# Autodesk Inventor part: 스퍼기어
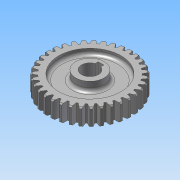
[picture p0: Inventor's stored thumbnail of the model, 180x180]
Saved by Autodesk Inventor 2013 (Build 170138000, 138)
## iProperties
Created: 2013-08
Part Number: 스퍼기어
Material: 강
Document SubType Name: Modeling
Designer: 한국산업디자인학원
Categories: <?xml version="1.0" encoding="UTF-16"?> <MemberInstance><Categories><FamilyTemplate><FamilyTemplateParameter ValueType="xs:double" Id="1" ObjectReferenceKey="da
Density: 1 g/cm^3
CustomPartVersion: 1
Author: 한국산업디자인학원
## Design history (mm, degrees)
sketch "Sketch1"
  geometry: C1 r 37 at (0, 0)
  constraints: 1 centre point
  dimensions: "d0" = 74 diameter of C1 (= da_da)
extrude "Extrusion1" new body sketch "Sketch1" distance "d1" = 15 (= da_b); taper "d2" = 0 deg
chamfer "모따기1" distance "d49" = 1; stored, may be unused: second distance "d50" = 2, angle "d51" = 45 deg
workplane "Work Plane2"
feature "피치 지름" dims "d4" = 10, "d5" = 0
workplane "Work Plane8"
workplane "Work Plane9"
feature "스퍼 기어" dims "da_b" = 15, "da_d" = 70, "da_aw" = 70, "da_da" = 74, "da_df" = 65, "da_dw" = 70, angle "da_beta" = 0 deg, "da_lefttooth" = 0, "da_righttooth" = 0
sketch "스케치3"
  geometry: L1 (-2.5, 7.071)-(-2.5, 9.8); L2 (-2.5, 9.8)-(2.5, 9.8); L3 (2.5, 9.8)-(2.5, 7.071); C1 r 27.5 at (0, 0); C2 r 12.5 at (0, 0); A1 r 36 centre (0, 0) between (-5.215, 35.62) and (-7.633, 35.181) reference; A2 r 7.5 centre (0, 0) between (-2.5, 7.071) and (2.5, 7.071)
  constraints: 6 end point, 3 centre point, 3 coincident, 2 parallel, 2 point on circle, 1 perpendicular, 1 vertical
  dimensions: "d52" = 55 diameter of C1; "d54" = 25 diameter of C2; "d55" = 15 diameter of A2; "d56" = 5 distance of L1.end L2.end; "d57" = 17.3 dimension on A2 L2
extrude "돌출2" cut sketch "스케치3" distance "d58" = 5; taper "d59" = 0 deg
node "작업 평면11"
node "작업 평면12"
sketch "스케치4"
  geometry: C1 r 12.5 at (0, 0); 1 further point
  constraints: 1 centre point, 1 coincident
  dimensions: "d61" = 25 diameter of C1
extrude "돌출3" join sketch "스케치4" distance "d63" = 31; taper "d64" = 0 deg
sketch "스케치5"
  geometry: L1 (-2.5, 7.071)-(-2.5, 9.8); L2 (-2.5, 9.8)-(2.5, 9.8); L3 (2.5, 9.8)-(2.5, 7.071); C1 r 12.5 at (0, 0) reference; A1 r 7.5 centre (0, 0) between (-2.5, 7.071) and (2.5, 7.071)
  constraints: 6 end point, 2 parallel, 2 point on circle, 1 centre point, 1 coincident, 1 perpendicular, 1 vertical
  dimensions: "d65" = 15 diameter of A1; "d67" = 17.3 dimension on A1 L2; "d68" = 5 distance of L1.end L2.end
extrude "돌출4" cut sketch "스케치5" stored distance "d69" = 31; taper "d70" = 0 deg
fillet "모깎기1" dims "d71" = 3
body "Solid1"
mirror "대칭1"
sketch "Sketch2"
  geometry: C1 r 37 at (0, 0) reference; C2 r 35 at (0, 0)
  constraints: 1 centre point, 1 coincident
  dimensions: "d3" = 70 diameter of C2 (= da_dw)
body "Srf1"
other parameters: "d17" = 0, "d34" = 0.8976 (computed from da_z), "d39" = 0, "d41" = 0, "d47" = 0, "d48" = 0, "d60" = 3
